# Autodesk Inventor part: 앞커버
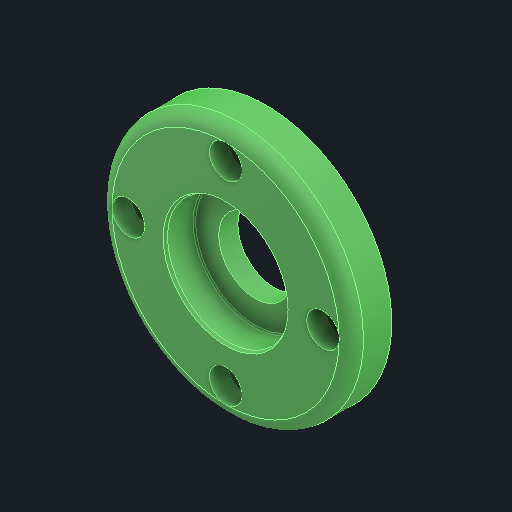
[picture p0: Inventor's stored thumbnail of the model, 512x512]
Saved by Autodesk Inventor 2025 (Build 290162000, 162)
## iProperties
Created: 2025-08
Part Number: 앞커버
Material: 알루미늄 6061
Document SubType Name: Modeling
Designer: infra15
Density: 2.71 g/cm^3
Appearance: 기본값
Author: jhkim
Sending System: Autodesk Inventor 2026
Preprocessor: ST-DEVELOPER v20.1
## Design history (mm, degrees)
feature "솔리드1"
node "솔리드2"
